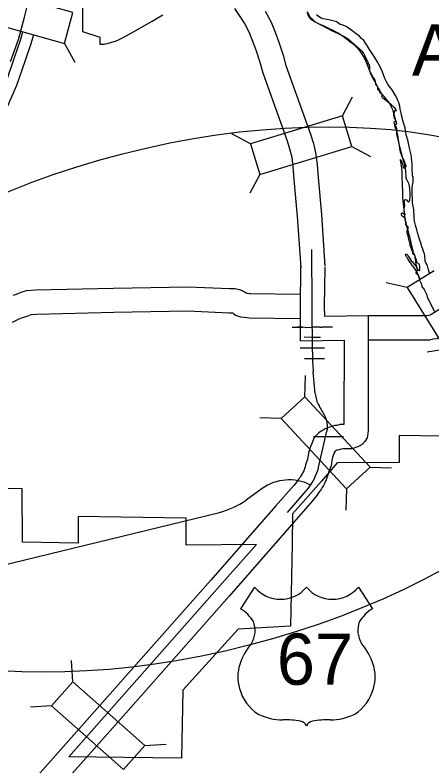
# Model space of a CAD drawing. Extents: x 813775 to 1157140, y 1757555 to 1979907.
# Drawn here: x 854634 to 864948, y 1925179 to 1943761 of the extents above; entities that cross this region are included whole.
import ezdxf

# ---------------------------------------------------------------- set-up
doc = ezdxf.new("R2010")
doc.units = 0
for name, color, linetype in [('1', 7, 'Continuous'), ('Level 10', 7, 'Continuous'), ('Level 15', 7, 'Continuous'), ('Level 19', 7, 'Continuous'), ('Level 20', 7, 'Continuous'), ('Level 22', 7, 'Continuous'), ('Level 6', 7, 'Continuous'), ('Level 9', 7, 'Continuous'), ('R_Draft', 7, 'Continuous')]:
    doc.layers.add(name, color=color, linetype=linetype)

msp = doc.modelspace()

# ---------------------------------------------------------------- linework, layer by layer
at = {"layer": '1'}
for p, q in [((861988, 1936562), (861976, 1937961)), ((861990, 1935425), (861988, 1936562)), ((861489, 1936036), (861749, 1936037)), ((861749, 1936037), (861610, 1936037)), ((861809, 1936033), (861749, 1936037)), ((861809, 1936033), (861989, 1936034)), ((862171, 1936034), (861989, 1936034)), ((862171, 1936034), (862231, 1936039)), ((862489, 1936039), (862231, 1936039)), ((861789, 1935795), (861989, 1935794)), ((861989, 1935794), (862189, 1935794)), ((861689, 1935524), (861989, 1935526)), ((861989, 1935526), (862289, 1935528)), ((861792, 1935263), (861992, 1935263)), ((861992, 1935263), (862292, 1935263)), ((862059, 1934392), (862012, 1934927)), ((862291, 1933860), (862154, 1934094)), ((862153, 1932605), (862351, 1933462)), ((862021, 1933331), (862321, 1933334)), ((862322, 1933336), (862373, 1933333)), ((861930, 1932137), (861946, 1932128)), ((860746, 1932044), (860349, 1931759)), ((861372, 1931452), (861838, 1931987)), ((854270, 1930132), (859688, 1931454))]:
    msp.add_line(p, q, dxfattribs=at)
for centre, radius, start, end in [((867719, 1935433), 5730, 180.084, 185.0707), ((862773, 1934455), 716, 185.0707, 210.2413), ((861819, 1933585), 546, 346.9833, 30.2413), ((862574, 1937148), 3820, 266.9833, 272.761), ((860757, 1932927), 1432, 318.9583, 346.9833), ((861415, 1931113), 1146, 63.2899, 125.6971), ((859235, 1933310), 1910, 283.7123, 305.6971)]:
    msp.add_arc(centre, radius, start, end, dxfattribs=at)
at = {"layer": 'Level 10'}
for points in [[(854584, 1936829), (854669, 1936856), (854732, 1936876), (854811, 1936908), (854918, 1936944), (855144, 1936961), (857067, 1937004), (858908, 1937039), (859940, 1936994), (860072, 1936996), (860186, 1936973), (860249, 1936942), (860264, 1936935), (860326, 1936904), (860365, 1936880), (860430, 1936872), (860460, 1936869), (861689, 1936854)], [(863368, 1936323), (864822, 1936327), (864870, 1936338), (864907, 1936343), (864941, 1936370), (865378, 1936642), (865536, 1936723), (865663, 1936758), (865779, 1936746), (865864, 1936735), (865937, 1936728), (866034, 1936720), (866137, 1936703), (866188, 1936688)], [(854569, 1936159), (854652, 1936203), (854720, 1936235), (854792, 1936265), (854855, 1936285), (854936, 1936312), (855018, 1936344), (855039, 1936351), (855173, 1936361), (857079, 1936405), (858900, 1936438), (859931, 1936394), (860002, 1936395), (860010, 1936391), (860031, 1936381), (860035, 1936378), (860090, 1936337), (860210, 1936291), (860298, 1936283), (860367, 1936275), (860429, 1936269), (861678, 1936254)], [(863380, 1935723), (864892, 1935727), (864980, 1935747), (865073, 1935761), (865208, 1935817), (865286, 1935878), (865674, 1936119), (865729, 1936147), (865796, 1936139), (865808, 1936138)]]:
    msp.add_lwpolyline(points, dxfattribs=at)
at = {"layer": 'Level 15'}
for points in [[(860061, 1943925), (860307, 1943552), (860422, 1943330), (860512, 1943117), (860590, 1942896), (860689, 1942595), (860762, 1942334), (861367, 1940647), (861434, 1940427), (861478, 1940240), (861508, 1940006), (861531, 1939693), (861615, 1938774), (861700, 1937510)], [(860825, 1943856), (860966, 1943586), (861072, 1943334), (861158, 1943089), (861263, 1942769), (861334, 1942516), (861936, 1940836), (862014, 1940583), (862069, 1940347), (862105, 1940066), (862129, 1939743), (862213, 1938822), (862299, 1937550)], [(861699, 1937534), (861685, 1936552), (861688, 1935703)], [(862299, 1937526), (862285, 1936549), (862286, 1936312)], [(862286, 1936312), (863373, 1936327), (863368, 1933707), (863372, 1933495), (863363, 1933399), (863346, 1933300), (863285, 1933210), (863218, 1933137), (863146, 1933094), (863091, 1933069), (863059, 1933058), (862983, 1933028), (862819, 1933029), (862747, 1933027), (862695, 1933016), (862684, 1933014), (862651, 1933003), (862613, 1932996), (862592, 1932990), (862587, 1932988), (862578, 1932984), (862548, 1932967), (862546, 1932966), (862541, 1932954), (862519, 1932909), (862508, 1932883), (862502, 1932866), (862485, 1932812), (862474, 1932737), (862455, 1932609), (862431, 1932546), (862414, 1932502), (862391, 1932444), (862381, 1932408), (862332, 1932258), (862295, 1932182), (862265, 1932120), (862232, 1932071), (862214, 1932037), (862169, 1931968), (862128, 1931913), (862096, 1931870), (862051, 1931813), (861996, 1931741), (861531, 1931211), (859930, 1929382), (857371, 1926490), (855128, 1923958)], [(861688, 1935703), (862772, 1935718), (862768, 1933703), (862770, 1933628), (862675, 1933625), (862595, 1933608), (862546, 1933602), (862498, 1933585), (862473, 1933580), (862413, 1933563), (862371, 1933549), (862308, 1933521), (862254, 1933490), (862204, 1933462), (862149, 1933421), (862092, 1933367), (862028, 1933287), (861992, 1933196), (861973, 1933158), (861948, 1933099), (861933, 1933056), (861898, 1932950), (861880, 1932825), (861871, 1932761), (861870, 1932760), (861855, 1932720), (861821, 1932634), (861807, 1932581), (861775, 1932484), (861755, 1932443), (861745, 1932422), (861718, 1932383), (861696, 1932341), (861676, 1932310), (861648, 1932273), (861621, 1932237), (861577, 1932181), (861531, 1932121), (861080, 1931606), (859480, 1929779), (856922, 1926888), (854678, 1924355)]]:
    msp.add_lwpolyline(points, dxfattribs=at)
at = {"layer": 'Level 19'}
for points in [[(852376, 1937320), (852985, 1938731), (853323, 1939554), (853618, 1940229), (853841, 1940759), (853984, 1941112), (854114, 1941413), (854422, 1942128), (854621, 1942709), (854770, 1943141), (854829, 1943345)], [(852629, 1937211), (853238, 1938624), (853576, 1939446), (853871, 1940121), (854095, 1940654), (854238, 1941006), (854366, 1941305), (854679, 1942029), (854881, 1942620), (855032, 1943058), (855097, 1943279)]]:
    msp.add_lwpolyline(points, dxfattribs=at)
at = {"layer": 'Level 20'}
for p, q in [((855854, 1943059), (856113, 1942598)), ((862734, 1941267), (862982, 1941733)), ((860461, 1940575), (859995, 1940823)), ((862964, 1940509), (863430, 1940261)), ((860691, 1939817), (860443, 1939351)), ((865004, 1937433), (864332, 1937015)), ((864332, 1937015), (863818, 1937135)), ((864332, 1937015), (865586, 1934997)), ((865352, 1935500), (864831, 1935415)), ((861802, 1934317), (861822, 1934845)), ((861221, 1933778), (860693, 1933798)), ((863417, 1932575), (863945, 1932555)), ((862837, 1932036), (862817, 1931509)), ((856065, 1927260), (856033, 1927787)), ((855540, 1926667), (855013, 1926635)), ((857844, 1925684), (858371, 1925716))]:
    msp.add_line(p, q, dxfattribs=at)
for points in [[(853567, 1943701), (855854, 1943059), (856068, 1943821), (853781, 1944463)], [(862734, 1941267), (860461, 1940575), (860691, 1939817), (862964, 1940509)], [(861221, 1933778), (862837, 1932036), (863417, 1932575), (861802, 1934317)], [(855540, 1926667), (857319, 1925091), (857844, 1925684), (856065, 1927260)]]:
    msp.add_lwpolyline(points, close=True, dxfattribs=at)
at = {"layer": 'Level 22'}
for p, q in [((860557, 1929604), (860211, 1929069)), ((863131, 1929604), (863477, 1929069))]:
    msp.add_line(p, q, dxfattribs=at)
for centre, radius, start, end in [((861202, 1930147), 842, 220.075, 319.6701), ((862486, 1930147), 842, 220.3299, 319.925), ((859758, 1928292), 899, 30.7809, 59.9883), ((863929, 1928292), 899, 120.0117, 149.2191), ((859956, 1928529), 617, 328.8105, 21.2108), ((863731, 1928529), 617, 158.7892, 211.1895), ((861569, 1927265), 1438, 138.9565, 162.6913), ((862119, 1927265), 1438, 17.3087, 41.0435), ((861094, 1927383), 950, 160.9576, 197.3819), ((862594, 1927383), 950, 342.6181, 19.0424), ((861248, 1927386), 1100, 195.1074, 237.1312), ((862439, 1927386), 1100, 302.8688, 344.8926), ((861269, 1927732), 1412, 244.0771, 269.5779), ((862419, 1927732), 1412, 270.4221, 295.9229), ((861302, 1923734), 2587, 81.1942, 90.9539), ((861625, 1926053), 248, 28.0342, 72.9864), ((862063, 1926053), 248, 107.0136, 151.9658), ((862386, 1923734), 2587, 89.0461, 98.8058)]:
    msp.add_arc(centre, radius, start, end, dxfattribs=at)
at = {"layer": 'Level 6'}
for points in [[(854521, 1942612), (854723, 1943158), (854866, 1943711), (854940, 1944005)], [(856300, 1944007), (856299, 1943352), (856732, 1943213), (856732, 1943037), (856794, 1943038), (856837, 1943039), (856863, 1943045), (856917, 1943055), (856967, 1943070), (857119, 1943117), (857214, 1943157), (857307, 1943202), (857620, 1943377), (857898, 1943537), (858025, 1943607), (858151, 1943683), (858289, 1943764)], [(861864, 1943801), (861884, 1943758), (861914, 1943702), (861924, 1943689), (861934, 1943679), (861945, 1943669), (861962, 1943655), (861991, 1943635), (862059, 1943595), (862199, 1943518), (862352, 1943439), (862482, 1943372), (862613, 1943309), (862694, 1943272), (862746, 1943247), (862790, 1943224)], [(862790, 1943224), (862829, 1943199), (862861, 1943177), (862893, 1943152), (863023, 1943039), (863101, 1942973), (863136, 1942944), (863208, 1942876), (863255, 1942819), (863286, 1942753), (863315, 1942695), (863331, 1942656), (863349, 1942622), (863368, 1942560), (863391, 1942527), (863401, 1942470), (863399, 1942428), (863401, 1942407), (863404, 1942391), (863408, 1942366), (863421, 1942336), (863435, 1942310), (863448, 1942288), (863469, 1942248), (863508, 1942203), (863524, 1942177), (863535, 1942155), (863547, 1942075), (863553, 1942047), (863558, 1942035), (863576, 1942016), (863588, 1941997), (863598, 1941978), (863598, 1941949), (863602, 1941930), (863609, 1941917), (863637, 1941893), (863644, 1941881), (863650, 1941862), (863668, 1941839), (863689, 1941819), (863707, 1941807), (863714, 1941795), (863715, 1941780), (863703, 1941763), (863703, 1941751), (863708, 1941736), (863715, 1941724), (863730, 1941708), (863801, 1941663), (863925, 1941562), (864014, 1941473), (864042, 1941432), (864048, 1941418), (864059, 1941389), (864057, 1941387), (864053, 1941385), (864014, 1941387), (864012, 1941382), (864012, 1941372), (864012, 1941337), (864001, 1941315), (864000, 1941298), (863999, 1941278), (864009, 1941245), (864007, 1941228), (864018, 1941204), (864034, 1941171), (864049, 1941138), (864049, 1941123), (864036, 1941115), (864009, 1941117), (864007, 1941105), (864016, 1941078), (864036, 1941023), (864059, 1940988), (864067, 1940945), (864075, 1940885), (864072, 1940847), (864074, 1940812), (864094, 1940722), (864101, 1940681), (864110, 1940636), (864125, 1940573), (864151, 1940477), (864190, 1940321), (864236, 1940163), (864258, 1940091), (864268, 1940039), (864268, 1940019), (864295, 1939932), (864297, 1939887), (864303, 1939755), (864303, 1939716), (864322, 1939683), (864365, 1939597), (864382, 1939529), (864392, 1939465), (864399, 1939340), (864398, 1939249)], [(864398, 1939249), (864394, 1939209), (864388, 1939169), (864384, 1939154), (864377, 1939140), (864371, 1939128), (864363, 1939130), (864353, 1939146), (864351, 1939160), (864350, 1939170), (864339, 1939173), (864314, 1939182), (864295, 1939188), (864287, 1939190), (864279, 1939190), (864274, 1939187), (864269, 1939183), (864266, 1939173), (864264, 1939159), (864263, 1939139), (864264, 1939111), (864266, 1939050), (864259, 1939002), (864253, 1938967), (864251, 1938917), (864253, 1938888), (864259, 1938856), (864277, 1938832), (864280, 1938823), (864281, 1938813), (864275, 1938813), (864267, 1938819), (864256, 1938832), (864229, 1938851), (864215, 1938856), (864202, 1938857), (864190, 1938854), (864186, 1938850), (864182, 1938842), (864182, 1938833), (864186, 1938821), (864213, 1938795), (864271, 1938749), (864278, 1938735), (864280, 1938715), (864277, 1938692), (864279, 1938682), (864283, 1938675), (864293, 1938663), (864299, 1938647), (864291, 1938605), (864291, 1938589), (864295, 1938574), (864302, 1938568), (864320, 1938556), (864335, 1938544), (864345, 1938535), (864348, 1938524), (864349, 1938513), (864350, 1938492), (864349, 1938469), (864328, 1938432), (864324, 1938406), (864328, 1938379), (864351, 1938301), (864373, 1938173), (864388, 1938142), (864404, 1938070), (864458, 1937916), (864470, 1937869), (864484, 1937850), (864513, 1937830), (864525, 1937764), (864532, 1937718), (864542, 1937679), (864550, 1937585), (864575, 1937500), (864581, 1937453), (864579, 1937430), (864560, 1937414), (864551, 1937392), (864550, 1937381), (864560, 1937365), (864576, 1937356), (864591, 1937340), (864599, 1937329), (864608, 1937313), (864622, 1937270), (864637, 1937233), (864643, 1937202), (864659, 1937165), (864680, 1937116), (864686, 1937087), (864708, 1937029), (864727, 1937011), (864752, 1936972), (864811, 1936856), (864848, 1936741), (864869, 1936708), (864891, 1936651)], [(864891, 1936651), (864943, 1936560), (864998, 1936437)], [(866763, 1933313), (864139, 1933356), (864133, 1932691), (862606, 1932681), (862215, 1932225), (861497, 1931419), (861491, 1930669), (861452, 1928643), (860152, 1928562), (858785, 1927052), (858748, 1925374)], [(858748, 1925374), (856634, 1925395), (855964, 1925407), (858328, 1928084), (859317, 1929204), (859891, 1929853), (860606, 1930660), (858866, 1930641), (858871, 1931313), (856199, 1931356), (856195, 1930691), (854819, 1930716), (854814, 1932040), (853531, 1932057)]]:
    msp.add_lwpolyline(points, dxfattribs=at)
at = {"layer": 'Level 9'}
for points in [[(861854, 1943838), (861908, 1943752), (861927, 1943714), (861964, 1943677), (862003, 1943634), (862016, 1943633), (862060, 1943596), (862146, 1943542), (862253, 1943499), (862388, 1943435), (862479, 1943391), (862615, 1943317), (862749, 1943234), (862827, 1943177), (862919, 1943107), (863006, 1943039), (863107, 1942938), (863202, 1942807), (863269, 1942702), (863322, 1942592), (863372, 1942467), (863426, 1942316), (863478, 1942210), (863539, 1942099), (863617, 1941949), (863665, 1941870), (863703, 1941815), (863751, 1941751), (863790, 1941706), (863839, 1941643), (863889, 1941576), (863910, 1941547), (863950, 1941474), (863971, 1941427), (863994, 1941325), (864029, 1941220), (864055, 1941133), (864066, 1941095), (864069, 1941067), (864061, 1941055), (864034, 1941046), (864025, 1941048), (864018, 1941043), (864022, 1941018), (864050, 1940940), (864075, 1940855), (864100, 1940751), (864112, 1940662), (864124, 1940582), (864134, 1940528), (864145, 1940460), (864164, 1940379), (864203, 1940268), (864224, 1940220), (864241, 1940185), (864258, 1940149), (864269, 1940122), (864275, 1940092), (864296, 1940052), (864301, 1940038), (864298, 1940008), (864294, 1940002), (864282, 1939990), (864274, 1939982), (864259, 1939975), (864249, 1939975), (864246, 1939983), (864242, 1939993), (864239, 1940019), (864233, 1940047), (864222, 1940080), (864211, 1940104), (864207, 1940120), (864196, 1940146), (864192, 1940153), (864179, 1940173), (864173, 1940179), (864165, 1940185), (864161, 1940185), (864159, 1940169), (864173, 1940121), (864180, 1940079), (864183, 1940027), (864191, 1939963), (864202, 1939870), (864203, 1939808), (864205, 1939733), (864207, 1939613), (864210, 1939557), (864221, 1939388), (864222, 1939268), (864229, 1939154), (864245, 1939016)], [(864828, 1937562), (864781, 1937670), (864773, 1937803), (864762, 1937851), (864742, 1937909), (864719, 1937964), (864697, 1938024), (864679, 1938103), (864647, 1938194), (864629, 1938242), (864614, 1938295), (864592, 1938377), (864572, 1938446), (864541, 1938564), (864518, 1938659), (864508, 1938749), (864504, 1938829), (864500, 1938881), (864496, 1938943), (864491, 1938989), (864484, 1939035), (864468, 1939114), (864467, 1939148), (864462, 1939248), (864459, 1939306), (864457, 1939372), (864459, 1939424), (864461, 1939494), (864468, 1939553), (864482, 1939627), (864480, 1939757), (864470, 1939779), (864462, 1939839), (864458, 1939915), (864460, 1939995), (864458, 1940059), (864448, 1940147), (864439, 1940236), (864431, 1940304), (864418, 1940370), (864402, 1940436), (864386, 1940499), (864375, 1940553), (864359, 1940628), (864343, 1940692), (864332, 1940722), (864312, 1940799), (864295, 1940903), (864285, 1940967), (864246, 1941094), (864230, 1941151), (864212, 1941225), (864193, 1941286), (864185, 1941332), (864163, 1941430), (864151, 1941508), (864135, 1941563), (864120, 1941613), (864097, 1941662), (864075, 1941716), (864044, 1941773), (863985, 1941865), (863960, 1941909), (863923, 1941956), (863867, 1942036), (863814, 1942123), (863783, 1942188), (863740, 1942303), (863692, 1942430), (863633, 1942536), (863589, 1942615), (863535, 1942710), (863470, 1942810), (863401, 1942908), (863349, 1942989), (863307, 1943062), (863259, 1943132), (863206, 1943183), (863151, 1943234), (863069, 1943299), (862963, 1943380), (862884, 1943438), (862843, 1943467), (862766, 1943501), (862695, 1943529), (862663, 1943536), (862594, 1943591), (862531, 1943611), (862465, 1943625), (862399, 1943639), (862347, 1943648), (862258, 1943665), (862206, 1943686), (862167, 1943707), (862135, 1943732), (862092, 1943763)], [(864245, 1939016), (864259, 1938878), (864276, 1938741), (864291, 1938641), (864309, 1938563), (864340, 1938464), (864371, 1938359), (864389, 1938279), (864443, 1938051), (864483, 1937894), (864517, 1937822), (864532, 1937773), (864556, 1937701), (864568, 1937658)], [(864468, 1937555), (864425, 1937622), (864410, 1937637), (864392, 1937661), (864373, 1937684), (864360, 1937708), (864354, 1937722), (864342, 1937742), (864333, 1937753), (864323, 1937767), (864319, 1937777), (864306, 1937795), (864298, 1937818), (864297, 1937836), (864297, 1937846), (864307, 1937847), (864309, 1937847), (864323, 1937841), (864339, 1937824), (864358, 1937794), (864373, 1937770), (864408, 1937717), (864437, 1937680), (864462, 1937651), (864487, 1937623), (864511, 1937596), (864530, 1937571), (864549, 1937549), (864557, 1937537), (864574, 1937510), (864582, 1937490), (864593, 1937472), (864597, 1937466), (864603, 1937454), (864611, 1937445), (864631, 1937443), (864637, 1937443), (864645, 1937450), (864649, 1937462), (864650, 1937474), (864648, 1937482), (864650, 1937498), (864649, 1937510), (864647, 1937524), (864645, 1937536), (864638, 1937574), (864637, 1937588), (864568, 1937658)], [(864468, 1937555), (864569, 1937416), (864601, 1937350), (864628, 1937268), (864644, 1937232)], [(864828, 1937562), (864855, 1937461), (864879, 1937381), (864882, 1937373)]]:
    msp.add_lwpolyline(points, dxfattribs=at)
at = {"layer": 'R_Draft'}
msp.add_ellipse((858856, 1934247), major_axis=(11387, 2926), ratio=0.533954, dxfattribs=at)

# ---------------------------------------------------------------- texts
at = {"layer": 'Level 22'}
msp.add_text('67', height=1267.2, dxfattribs=at).set_placement((861111, 1927189))
at = {"layer": 'Level 6'}
msp.add_text('ARKADELPHIA', height=1267.2, dxfattribs=at).set_placement((864454, 1942264))

doc.saveas('drawing.dxf')
